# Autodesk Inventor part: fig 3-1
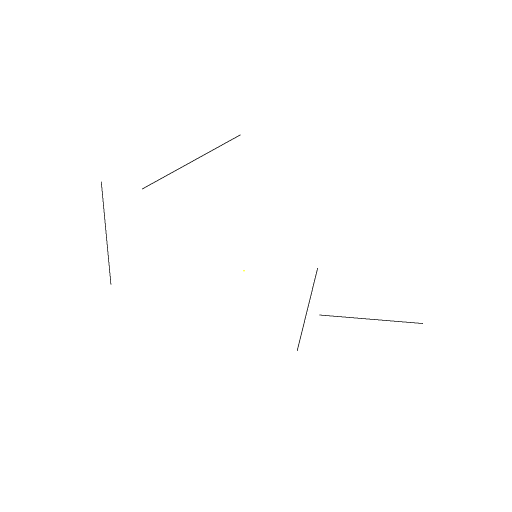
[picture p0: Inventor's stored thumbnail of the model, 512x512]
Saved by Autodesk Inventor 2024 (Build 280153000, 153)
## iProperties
Created: 2011-07
Part Number: fig 3-1
Material: Generic
Document SubType Name: Modeling
Designer: CadCim
Density: 1 g/cm^3
Appearance: Default
Author: CadCim
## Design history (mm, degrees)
sketch "Sketch1"
  geometry: L1 (-24.535, 0.895)-(-9.053, -12.994); L2 (-20.147, 3.302)-(-19.785, 19.15); L3 (5.706, 6.44)-(15.874, -7.118); L4 (12.565, -0.112)-(22.33, 7.212); 1 further point
  constraints: 8 end point, 1 perpendicular, 1 other
